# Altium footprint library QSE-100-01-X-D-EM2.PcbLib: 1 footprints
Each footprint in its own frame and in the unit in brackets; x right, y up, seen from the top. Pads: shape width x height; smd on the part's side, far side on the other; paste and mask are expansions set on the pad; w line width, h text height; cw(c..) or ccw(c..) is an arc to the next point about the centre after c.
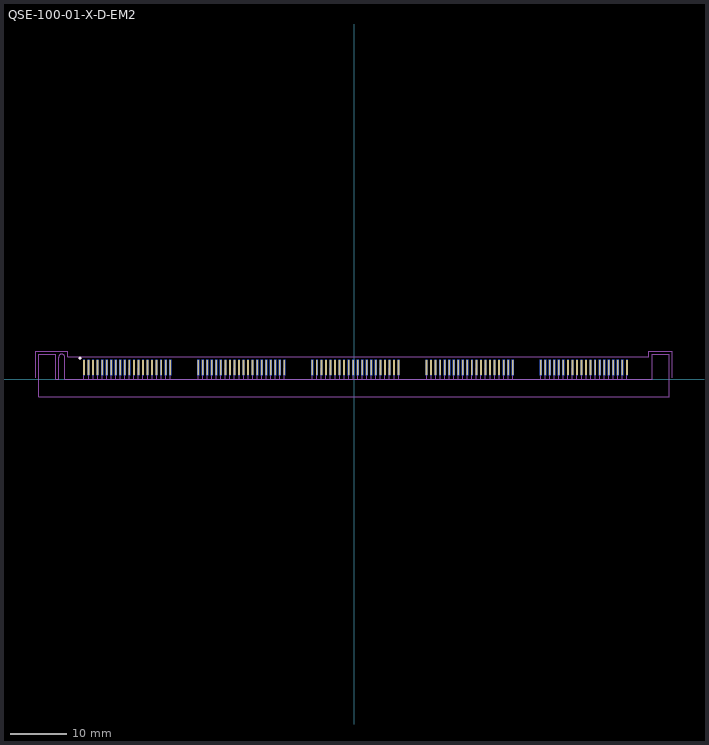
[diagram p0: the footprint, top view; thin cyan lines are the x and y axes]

## QSE-100-01-X-D-EM2 [mil] "0.80mm pitch, 200 pin, high speed socket; w/edge mounts"
height 142.91
pads (200):
  rect 12.01x105 smd far side mask+0: 1(-1874.25,82.5) 3(-1842.76,82.5) 5(-1811.26,82.5) 7(-1779.76,82.5) 9(-1748.27,82.5) 11(-1716.77,82.5) 13(-1685.28,82.5) 15(-1653.78,82.5) 17(-1622.28,82.5) 19(-1590.79,82.5) 21(-1559.29,82.5) 23(-1527.8,82.5) 25(-1496.3,82.5) 27(-1464.8,82.5) 29(-1433.31,82.5) 31(-1401.81,82.5) 33(-1370.32,82.5) 35(-1338.82,82.5) 37(-1307.32,82.5) 39(-1275.83,82.5) 41(-1081.73,82.5) 43(-1050.24,82.5) 45(-1018.74,82.5) 47(-987.24,82.5) 49(-955.75,82.5) 51(-924.25,82.5) 53(-892.76,82.5) 55(-861.26,82.5) 57(-829.76,82.5) 59(-798.27,82.5) 61(-766.77,82.5) 63(-735.28,82.5) 65(-703.78,82.5) 67(-672.28,82.5) 69(-640.79,82.5) 71(-609.29,82.5) 73(-577.8,82.5) 75(-546.3,82.5) 77(-514.8,82.5) 79(-483.31,82.5) 81(-289.21,82.5) 83(-257.72,82.5) 85(-226.22,82.5) 87(-194.72,82.5) 89(-163.23,82.5) 91(-131.73,82.5) 93(-100.24,82.5) 95(-68.74,82.5) 97(-37.24,82.5) 99(-5.75,82.5) 101(25.75,82.5) 103(57.24,82.5) 105(88.74,82.5) 107(120.24,82.5) 109(151.73,82.5) 111(183.23,82.5) 113(214.72,82.5) 115(246.22,82.5) 117(277.72,82.5) 119(309.21,82.5) 121(503.31,82.5) 123(534.8,82.5) 125(566.3,82.5) 127(597.8,82.5) 129(629.29,82.5) 131(660.79,82.5) 133(692.28,82.5) 135(723.78,82.5) 137(755.28,82.5) 139(786.77,82.5) 141(818.27,82.5) 143(849.76,82.5) 145(881.26,82.5) 147(912.76,82.5) 149(944.25,82.5) 151(975.75,82.5) 153(1007.24,82.5) 155(1038.74,82.5) 157(1070.24,82.5) 159(1101.73,82.5) 161(1295.83,82.5) 163(1327.32,82.5) 165(1358.82,82.5) 167(1390.32,82.5) 169(1421.81,82.5) 171(1453.31,82.5) 173(1484.8,82.5) 175(1516.3,82.5) 177(1547.8,82.5) 179(1579.29,82.5) 181(1610.79,82.5) 183(1642.28,82.5) 185(1673.78,82.5) 187(1705.28,82.5) 189(1736.77,82.5) 191(1768.27,82.5) 193(1799.76,82.5) 195(1831.26,82.5) 197(1862.76,82.5) 199(1894.25,82.5)
  rect 12.01x105 smd mask+0: 2(-1874.25,82.5) 4(-1842.76,82.5) 6(-1811.26,82.5) 8(-1779.76,82.5) 10(-1748.27,82.5) 12(-1716.77,82.5) 14(-1685.28,82.5) 16(-1653.78,82.5) 18(-1622.28,82.5) 20(-1590.79,82.5) 22(-1559.29,82.5) 24(-1527.8,82.5) 26(-1496.3,82.5) 28(-1464.8,82.5) 30(-1433.31,82.5) 32(-1401.81,82.5) 34(-1370.32,82.5) 36(-1338.82,82.5) 38(-1307.32,82.5) 40(-1275.83,82.5) 42(-1081.73,82.5) 44(-1050.24,82.5) 46(-1018.74,82.5) 48(-987.24,82.5) 50(-955.75,82.5) 52(-924.25,82.5) 54(-892.76,82.5) 56(-861.26,82.5) 58(-829.76,82.5) 60(-798.27,82.5) 62(-766.77,82.5) 64(-735.28,82.5) 66(-703.78,82.5) 68(-672.28,82.5) 70(-640.79,82.5) 72(-609.29,82.5) 74(-577.8,82.5) 76(-546.3,82.5) 78(-514.8,82.5) 80(-483.31,82.5) 82(-289.21,82.5) 84(-257.72,82.5) 86(-226.22,82.5) 88(-194.72,82.5) 90(-163.23,82.5) 92(-131.73,82.5) 94(-100.24,82.5) 96(-68.74,82.5) 98(-37.24,82.5) 100(-5.75,82.5) 102(25.75,82.5) 104(57.24,82.5) 106(88.74,82.5) 108(120.24,82.5) 110(151.73,82.5) 112(183.23,82.5) 114(214.72,82.5) 116(246.22,82.5) 118(277.72,82.5) 120(309.21,82.5) 122(503.31,82.5) 124(534.8,82.5) 126(566.3,82.5) 128(597.8,82.5) 130(629.29,82.5) 132(660.79,82.5) 134(692.28,82.5) 136(723.78,82.5) 138(755.28,82.5) 140(786.77,82.5) 142(818.27,82.5) 144(849.76,82.5) 146(881.26,82.5) 148(912.76,82.5) 150(944.25,82.5) 152(975.75,82.5) 154(1007.24,82.5) 156(1038.74,82.5) 158(1070.24,82.5) 160(1101.73,82.5) 162(1295.83,82.5) 164(1327.32,82.5) 166(1358.82,82.5) 168(1390.32,82.5) 170(1421.81,82.5) 172(1453.31,82.5) 174(1484.8,82.5) 176(1516.3,82.5) 178(1547.8,82.5) 180(1579.29,82.5) 182(1610.79,82.5) 184(1642.28,82.5) 186(1673.78,82.5) 188(1705.28,82.5) 190(1736.77,82.5) 192(1768.27,82.5) 194(1799.76,82.5) 196(1831.26,82.5) 198(1862.76,82.5) 200(1894.25,82.5)
Top Overlay:
  circle w9.84: c-1901.57,147.64 r4.92
Top Solder:
  lines w5: -1874.25,82.5 -1874.25,134.98 ; -1842.76,82.5 -1842.76,134.98 ; -1811.26,82.5 -1811.26,134.98 ; -1779.76,82.5 -1779.76,134.98 ; -1748.27,82.5 -1748.27,134.98 ; -1716.77,82.5 -1716.77,134.98 ; -1685.28,82.5 -1685.28,134.98 ; -1653.78,82.5 -1653.78,134.98 ; -1622.28,82.5 -1622.28,134.98 ; -1590.79,82.5 -1590.79,134.98 ; -1559.29,82.5 -1559.29,134.98 ; -1527.8,82.5 -1527.8,134.98 ; -1496.3,82.5 -1496.3,134.98 ; -1464.8,82.5 -1464.8,134.98 ; -1433.31,82.5 -1433.31,134.98 ; -1401.81,82.5 -1401.81,134.98 ; -1370.32,82.5 -1370.32,134.98 ; -1338.82,82.5 -1338.82,134.98 ; -1307.32,82.5 -1307.32,134.98 ; -1275.83,82.5 -1275.83,134.98 ; -1081.73,82.5 -1081.73,134.98 ; -1050.24,82.5 -1050.24,134.98 ; -1018.74,82.5 -1018.74,134.98 ; -987.24,82.5 -987.24,134.98 ; -955.75,82.5 -955.75,134.98 ; -924.25,82.5 -924.25,134.98 ; -892.76,82.5 -892.76,134.98 ; -861.26,82.5 -861.26,134.98 ; -829.76,82.5 -829.76,134.98 ; -798.27,82.5 -798.27,134.98 ; -766.77,82.5 -766.77,134.98 ; -735.28,82.5 -735.28,134.98 ; -703.78,82.5 -703.78,134.98 ; -672.28,82.5 -672.28,134.98 ; -640.79,82.5 -640.79,134.98 ; -609.29,82.5 -609.29,134.98 ; -577.8,82.5 -577.8,134.98 ; -546.3,82.5 -546.3,134.98 ; -514.8,82.5 -514.8,134.98 ; -483.31,82.5 -483.31,134.98 ; -289.21,82.5 -289.21,134.98 ; -257.72,82.5 -257.72,134.98 ; -226.22,82.5 -226.22,134.98 ; -194.72,82.5 -194.72,134.98 ; -163.23,82.5 -163.23,134.98 ; -131.73,82.5 -131.73,134.98 ; -100.24,82.5 -100.24,134.98 ; -68.74,82.5 -68.74,134.98 ; -37.24,82.5 -37.24,134.98 ; -5.75,82.5 -5.75,134.98 ; 25.75,82.5 25.75,134.98 ; 57.24,82.5 57.24,134.98 ; 88.74,82.5 88.74,134.98 ; 120.24,82.5 120.24,134.98 ; 151.73,82.5 151.73,134.98 ; 183.23,82.5 183.23,134.98 ; 214.72,82.5 214.72,134.98 ; 246.22,82.5 246.22,134.98 ; 277.72,82.5 277.72,134.98 ; 309.21,82.5 309.21,134.98 ; 503.31,82.5 503.31,134.98 ; 534.8,82.5 534.8,134.98 ; 566.3,82.5 566.3,134.98 ; 597.8,82.5 597.8,134.98 ; 629.29,82.5 629.29,134.98 ; 660.79,82.5 660.79,134.98 ; 692.28,82.5 692.28,134.98 ; 723.78,82.5 723.78,134.98 ; 755.28,82.5 755.28,134.98 ; 786.77,82.5 786.77,134.98 ; 818.27,82.5 818.27,134.98 ; 849.76,82.5 849.76,134.98 ; 881.26,82.5 881.26,134.98 ; 912.76,82.5 912.76,134.98 ; 944.25,82.5 944.25,134.98 ; 975.75,82.5 975.75,134.98 ; 1007.24,82.5 1007.24,134.98 ; 1038.74,82.5 1038.74,134.98 ; 1070.24,82.5 1070.24,134.98 ; 1101.73,82.5 1101.73,134.98 ; 1295.83,82.5 1295.83,134.98 ; 1327.32,82.5 1327.32,134.98 ; 1358.82,82.5 1358.82,134.98 ; 1390.32,82.5 1390.32,134.98 ; 1421.81,82.5 1421.81,134.98 ; 1453.31,82.5 1453.31,134.98 ; 1484.8,82.5 1484.8,134.98 ; 1516.3,82.5 1516.3,134.98 ; 1547.8,82.5 1547.8,134.98 ; 1579.29,82.5 1579.29,134.98 ; 1610.79,82.5 1610.79,134.98 ; 1642.28,82.5 1642.28,134.98 ; 1673.78,82.5 1673.78,134.98 ; 1705.28,82.5 1705.28,134.98 ; 1736.77,82.5 1736.77,134.98 ; 1768.27,82.5 1768.27,134.98 ; 1799.76,82.5 1799.76,134.98 ; 1831.26,82.5 1831.26,134.98 ; 1862.76,82.5 1862.76,134.98 ; 1894.25,82.5 1894.25,134.98
Bottom Solder:
  lines w5: -1874.25,82.5 -1874.25,134.98 ; -1842.76,82.5 -1842.76,134.98 ; -1811.26,82.5 -1811.26,134.98 ; -1779.76,82.5 -1779.76,134.98 ; -1748.27,82.5 -1748.27,134.98 ; -1716.77,82.5 -1716.77,134.98 ; -1685.28,82.5 -1685.28,134.98 ; -1653.78,82.5 -1653.78,134.98 ; -1622.28,82.5 -1622.28,134.98 ; -1590.79,82.5 -1590.79,134.98 ; -1559.29,82.5 -1559.29,134.98 ; -1527.8,82.5 -1527.8,134.98 ; -1496.3,82.5 -1496.3,134.98 ; -1464.8,82.5 -1464.8,134.98 ; -1433.31,82.5 -1433.31,134.98 ; -1401.81,82.5 -1401.81,134.98 ; -1370.32,82.5 -1370.32,134.98 ; -1338.82,82.5 -1338.82,134.98 ; -1307.32,82.5 -1307.32,134.98 ; -1275.83,82.5 -1275.83,134.98 ; -1081.73,82.5 -1081.73,134.98 ; -1050.24,82.5 -1050.24,134.98 ; -1018.74,82.5 -1018.74,134.98 ; -987.24,82.5 -987.24,134.98 ; -955.75,82.5 -955.75,134.98 ; -924.25,82.5 -924.25,134.98 ; -892.76,82.5 -892.76,134.98 ; -861.26,82.5 -861.26,134.98 ; -829.76,82.5 -829.76,134.98 ; -798.27,82.5 -798.27,134.98 ; -766.77,82.5 -766.77,134.98 ; -735.28,82.5 -735.28,134.98 ; -703.78,82.5 -703.78,134.98 ; -672.28,82.5 -672.28,134.98 ; -640.79,82.5 -640.79,134.98 ; -609.29,82.5 -609.29,134.98 ; -577.8,82.5 -577.8,134.98 ; -546.3,82.5 -546.3,134.98 ; -514.8,82.5 -514.8,134.98 ; -483.31,82.5 -483.31,134.98 ; -289.21,82.5 -289.21,134.98 ; -257.72,82.5 -257.72,134.98 ; -226.22,82.5 -226.22,134.98 ; -194.72,82.5 -194.72,134.98 ; -163.23,82.5 -163.23,134.98 ; -131.73,82.5 -131.73,134.98 ; -100.24,82.5 -100.24,134.98 ; -68.74,82.5 -68.74,134.98 ; -37.24,82.5 -37.24,134.98 ; -5.75,82.5 -5.75,134.98 ; 25.75,82.5 25.75,134.98 ; 57.24,82.5 57.24,134.98 ; 88.74,82.5 88.74,134.98 ; 120.24,82.5 120.24,134.98 ; 151.73,82.5 151.73,134.98 ; 183.23,82.5 183.23,134.98 ; 214.72,82.5 214.72,134.98 ; 246.22,82.5 246.22,134.98 ; 277.72,82.5 277.72,134.98 ; 309.21,82.5 309.21,134.98 ; 503.31,82.5 503.31,134.98 ; 534.8,82.5 534.8,134.98 ; 566.3,82.5 566.3,134.98 ; 597.8,82.5 597.8,134.98 ; 629.29,82.5 629.29,134.98 ; 660.79,82.5 660.79,134.98 ; 692.28,82.5 692.28,134.98 ; 723.78,82.5 723.78,134.98 ; 755.28,82.5 755.28,134.98 ; 786.77,82.5 786.77,134.98 ; 818.27,82.5 818.27,134.98 ; 849.76,82.5 849.76,134.98 ; 881.26,82.5 881.26,134.98 ; 912.76,82.5 912.76,134.98 ; 944.25,82.5 944.25,134.98 ; 975.75,82.5 975.75,134.98 ; 1007.24,82.5 1007.24,134.98 ; 1038.74,82.5 1038.74,134.98 ; 1070.24,82.5 1070.24,134.98 ; 1101.73,82.5 1101.73,134.98 ; 1295.83,82.5 1295.83,134.98 ; 1327.32,82.5 1327.32,134.98 ; 1358.82,82.5 1358.82,134.98 ; 1390.32,82.5 1390.32,134.98 ; 1421.81,82.5 1421.81,134.98 ; 1453.31,82.5 1453.31,134.98 ; 1484.8,82.5 1484.8,134.98 ; 1516.3,82.5 1516.3,134.98 ; 1547.8,82.5 1547.8,134.98 ; 1579.29,82.5 1579.29,134.98 ; 1610.79,82.5 1610.79,134.98 ; 1642.28,82.5 1642.28,134.98 ; 1673.78,82.5 1673.78,134.98 ; 1705.28,82.5 1705.28,134.98 ; 1736.77,82.5 1736.77,134.98 ; 1768.27,82.5 1768.27,134.98 ; 1799.76,82.5 1799.76,134.98 ; 1831.26,82.5 1831.26,134.98 ; 1862.76,82.5 1862.76,134.98 ; 1894.25,82.5 1894.25,134.98
Mechanical 13:
  circle w9.84: c-1901.57,147.64 r4.92
  lines w3.94: -1874.25,0 -1874.25,82.5 ; -1842.76,0 -1842.76,82.5 ; -1811.26,0 -1811.26,82.5 ; -1779.76,0 -1779.76,82.5 ; -1748.27,0 -1748.27,82.5 ; -1716.77,0 -1716.77,82.5 ; -1685.28,0 -1685.28,82.5 ; -1653.78,0 -1653.78,82.5 ; -1622.28,0 -1622.28,82.5 ; -1590.79,0 -1590.79,82.5 ; -1559.29,0 -1559.29,82.5 ; -1527.8,0 -1527.8,82.5 ; -1496.3,0 -1496.3,82.5 ; -1464.8,0 -1464.8,82.5 ; -1433.31,0 -1433.31,82.5 ; -1401.81,0 -1401.81,82.5 ; -1370.32,0 -1370.32,82.5 ; -1338.82,0 -1338.82,82.5 ; -1307.32,0 -1307.32,82.5 ; -1275.83,0 -1275.83,82.5 ; -1081.73,0 -1081.73,82.5 ; -1050.24,0 -1050.24,82.5 ; -1018.74,0 -1018.74,82.5 ; -987.24,0 -987.24,82.5 ; -955.75,0 -955.75,82.5 ; -924.25,0 -924.25,82.5 ; -892.76,0 -892.76,82.5 ; -861.26,0 -861.26,82.5 ; -829.76,0 -829.76,82.5 ; -798.27,0 -798.27,82.5 ; -766.77,0 -766.77,82.5 ; -735.28,0 -735.28,82.5 ; -703.78,0 -703.78,82.5 ; -672.28,0 -672.28,82.5 ; -640.79,0 -640.79,82.5 ; -609.29,0 -609.29,82.5 ; -577.8,0 -577.8,82.5 ; -546.3,0 -546.3,82.5 ; -514.8,0 -514.8,82.5 ; -483.31,0 -483.31,82.5 ; -289.21,0 -289.21,82.5 ; -257.72,0 -257.72,82.5 ; -226.22,0 -226.22,82.5 ; -194.72,0 -194.72,82.5 ; -163.23,0 -163.23,82.5 ; -131.73,0 -131.73,82.5 ; -100.24,0 -100.24,82.5 ; -68.74,0 -68.74,82.5 ; -37.24,0 -37.24,82.5 ; -5.75,0 -5.75,82.5 ; 25.75,0 25.75,82.5 ; 57.24,0 57.24,82.5 ; 88.74,0 88.74,82.5 ; 120.24,0 120.24,82.5 ; 151.73,0 151.73,82.5 ; 183.23,0 183.23,82.5 ; 214.72,0 214.72,82.5 ; 246.22,0 246.22,82.5 ; 277.72,0 277.72,82.5 ; 309.21,0 309.21,82.5 ; 503.31,0 503.31,82.5 ; 534.8,0 534.8,82.5 ; 566.3,0 566.3,82.5 ; 597.8,0 597.8,82.5 ; 629.29,0 629.29,82.5 ; 660.79,0 660.79,82.5 ; 692.28,0 692.28,82.5 ; 723.78,0 723.78,82.5 ; 755.28,0 755.28,82.5 ; 786.77,0 786.77,82.5 ; 818.27,0 818.27,82.5 ; 849.76,0 849.76,82.5 ; 881.26,0 881.26,82.5 ; 912.76,0 912.76,82.5 ; 944.25,0 944.25,82.5 ; 975.75,0 975.75,82.5 ; 1007.24,0 1007.24,82.5 ; 1038.74,0 1038.74,82.5 ; 1070.24,0 1070.24,82.5 ; 1101.73,0 1101.73,82.5 ; 1295.83,0 1295.83,82.5 ; 1327.32,0 1327.32,82.5 ; 1358.82,0 1358.82,82.5 ; 1390.32,0 1390.32,82.5 ; 1421.81,0 1421.81,82.5 ; 1453.31,0 1453.31,82.5 ; 1484.8,0 1484.8,82.5 ; 1516.3,0 1516.3,82.5 ; 1547.8,0 1547.8,82.5 ; 1579.29,0 1579.29,82.5 ; 1610.79,0 1610.79,82.5 ; 1642.28,0 1642.28,82.5 ; 1673.78,0 1673.78,82.5 ; 1705.28,0 1705.28,82.5 ; 1736.77,0 1736.77,82.5 ; 1768.27,0 1768.27,82.5 ; 1799.76,0 1799.76,82.5 ; 1831.26,0 1831.26,82.5 ; 1862.76,0 1862.76,82.5 ; 1894.25,0 1894.25,82.5 ; -2188.88,-120.08 2188.88,-120.08 2188.88,175 2068.88,175 2068.88,0 -2007.24,0 -2007.24,153.5 ccw(c-2028.74,153.5) -2050.24,153.5 -2050.24,0 -2068.88,0 -2068.88,175 -2188.88,175 -2188.88,-120.08
  text ".Designator" at 0,0 h60
Mechanical 15:
  lines w1.97: -2208.66,9.84 -2208.66,194.88 -1988.19,194.88 -1988.19,155.51 2047.24,155.51 2047.24,194.88 2208.66,194.88 2208.66,9.84
Drill Drawing:
  lines w0.39: -2208.66,0 -2050.24,0 -2050.24,153.5 cw(c-2028.74,153.5) -2007.24,153.5 -2007.24,0 2208.66,0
